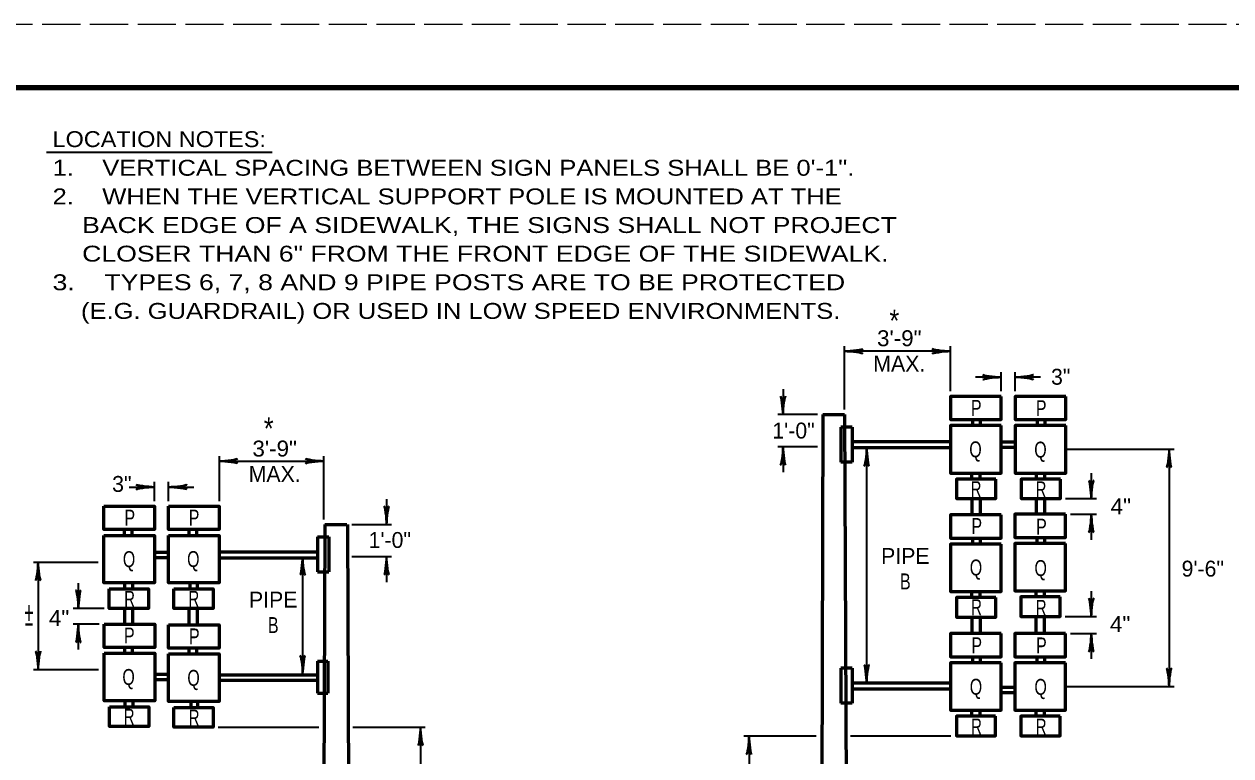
# Model space of a CAD drawing. Extents: x -209 to 471, y -242 to 199.
# Drawn here: x -54 to 135.5, y 83.5 to 198.5 of the extents above; entities that cross this region are included whole.
import ezdxf
from ezdxf.enums import TextEntityAlignment as Align

# ---------------------------------------------------------------- set-up
doc = ezdxf.new("R2010")
doc.units = 0
doc.linetypes.add('LONG_DASHED', pattern=[7.5, 6, -1.5])
doc.layers.add('1', color=7, linetype='Continuous', lineweight=53)
doc.layers.add('61', color=7, linetype='Continuous', lineweight=35)

msp = doc.modelspace()

# ---------------------------------------------------------------- linework, layer by layer
at = {"layer": '1', "lineweight": 35}
for p, q in [((-50.474, 178.398), (-15.047, 178.398)), ((74.868, 137.935), (74.868, 147.893)), ((91.488, 140.805), (91.488, 147.893)), ((91.488, 147.094), (74.868, 147.094)), ((99.434, 143.015), (95.441, 143.015)), ((99.434, 140.805), (99.434, 143.813)), ((101.648, 140.805), (101.648, 143.813)), ((105.641, 143.015), (101.648, 143.015)), ((65.201, 141.129), (65.201, 137.136)), ((70.633, 137.136), (64.402, 137.136)), ((70.633, 132.078), (64.402, 132.078)), ((65.201, 132.078), (65.201, 128.085)), ((78.33, 131.903), (78.33, 94.915)), ((109.594, 131.686), (126.631, 131.686)), ((125.832, 131.686), (125.832, 94.4)), ((-23.352, 129.823), (-6.91, 129.823)), ((-23.317, 123.534), (-23.317, 130.621)), ((-6.91, 120.663), (-6.91, 130.621)), ((113.605, 127.917), (113.605, 123.924)), ((-37.505, 125.743), (-33.512, 125.743)), ((-33.512, 123.534), (-33.512, 126.542)), ((-31.298, 123.534), (-31.298, 126.542)), ((-31.298, 125.743), (-27.305, 125.743)), ((2.935, 123.858), (2.935, 119.865)), ((109.552, 123.924), (114.403, 123.924)), ((110.339, 121.468), (114.403, 121.468)), ((113.605, 121.468), (113.605, 117.475)), ((-2.498, 119.865), (3.734, 119.865)), ((-52.505, 113.917), (-42.341, 113.917)), ((-51.779, 113.917), (-51.779, 97.063)), ((-10.241, 114.798), (-10.241, 96.392)), ((-2.498, 114.807), (3.734, 114.807)), ((2.935, 114.807), (2.935, 110.814)), ((-45.469, 110.645), (-45.469, 106.652)), ((113.605, 109.378), (113.605, 105.385)), ((-41.416, 106.652), (-46.267, 106.652)), ((109.499, 105.385), (114.403, 105.385)), ((-42.203, 104.197), (-46.267, 104.197)), ((-45.469, 104.197), (-45.469, 100.203)), ((110.339, 102.721), (114.403, 102.721)), ((113.605, 102.721), (113.605, 98.728)), ((-52.505, 97.063), (-42.293, 97.063)), ((109.541, 94.4), (126.631, 94.4)), ((-23.49, 88.009), (-7.724, 88.009)), ((-2.34, 88.009), (9.02, 88.009)), ((8.275, 88.009), (8.275, 58.346)), ((70.423, 86.607), (59.063, 86.607)), ((59.861, 86.607), (59.861, 56.943)), ((91.572, 86.607), (75.806, 86.607))]:
    msp.add_line(p, q, dxfattribs=at)
at = {"layer": '1'}
for p, q in [((71.432, 137.136), (71.21, 56.943)), ((71.432, 137.136), (74.868, 137.136)), ((74.868, 137.136), (75.201, 56.943)), ((76.031, 135.173), (74.285, 135.173)), ((74.285, 135.173), (74.285, 129.671)), ((76.031, 135.173), (76.031, 129.671)), ((95.004, 135.426), (95.004, 136.36)), ((96.189, 135.426), (96.189, 136.36)), ((105.164, 135.426), (105.164, 136.36)), ((106.349, 135.426), (106.349, 136.36)), ((91.455, 132.832), (76.031, 132.832)), ((101.723, 132.797), (99.509, 132.797)), ((91.455, 131.903), (76.031, 131.903)), ((101.723, 131.941), (99.509, 131.941)), ((76.031, 129.671), (74.285, 129.671)), ((94.871, 127.009), (94.871, 127.945)), ((96.162, 127.009), (96.162, 127.945)), ((105.031, 127.009), (105.031, 127.945)), ((106.322, 127.009), (106.322, 127.945)), ((94.897, 121.364), (94.897, 123.819)), ((96.189, 121.364), (96.189, 123.819)), ((105.031, 121.468), (105.031, 123.924)), ((106.322, 121.468), (106.322, 123.924)), ((-6.783, 119.865), (-6.954, 58.346)), ((-6.732, 119.865), (-3.296, 119.865)), ((-3.218, 119.865), (-2.963, 58.346)), ((-38.213, 118.154), (-38.213, 119.088)), ((-37.028, 118.154), (-37.028, 119.088)), ((-28.053, 118.154), (-28.053, 119.088)), ((-26.868, 118.154), (-26.868, 119.088)), ((-7.895, 117.901), (-6.149, 117.901)), ((-7.895, 117.901), (-7.895, 112.4)), ((-6.149, 117.901), (-6.149, 112.4)), ((95.004, 116.783), (95.004, 117.717)), ((96.189, 116.783), (96.189, 117.717)), ((105.111, 116.887), (105.111, 117.821)), ((106.295, 116.887), (106.295, 117.821)), ((-33.587, 115.526), (-31.374, 115.526)), ((-33.587, 114.669), (-31.374, 114.669)), ((-23.319, 115.561), (-7.895, 115.561)), ((-23.319, 114.632), (-7.895, 114.632)), ((-7.895, 112.4), (-6.149, 112.4)), ((-38.186, 109.738), (-38.186, 110.674)), ((-36.895, 109.738), (-36.895, 110.674)), ((-27.902, 109.761), (-27.902, 110.612)), ((-26.729, 109.761), (-26.729, 110.612)), ((94.871, 108.367), (94.871, 109.303)), ((96.162, 108.367), (96.162, 109.303)), ((104.978, 108.471), (104.978, 109.407)), ((106.269, 108.471), (106.269, 109.407)), ((-38.186, 104.197), (-38.186, 106.652)), ((-36.895, 104.197), (-36.895, 106.652)), ((-28.053, 104.092), (-28.053, 106.548)), ((-26.762, 104.092), (-26.762, 106.548)), ((94.895, 102.721), (94.895, 105.176)), ((96.186, 102.721), (96.186, 105.176)), ((104.978, 102.721), (104.978, 105.385)), ((106.269, 102.721), (106.269, 105.385)), ((-38.16, 99.616), (-38.16, 100.55)), ((-36.975, 99.616), (-36.975, 100.55)), ((-28.053, 99.511), (-28.053, 100.445)), ((-26.868, 99.511), (-26.868, 100.445)), ((95.002, 98.14), (95.002, 99.074)), ((96.186, 98.14), (96.186, 99.074)), ((105.111, 98.14), (105.111, 99.074)), ((106.295, 98.14), (106.295, 99.074)), ((-7.895, 98.353), (-6.308, 98.353)), ((-7.895, 98.353), (-7.895, 93.352)), ((-6.308, 98.353), (-6.308, 93.352)), ((76.031, 97.255), (74.285, 97.255)), ((74.285, 97.255), (74.285, 91.753)), ((76.031, 97.255), (76.031, 91.753)), ((-33.397, 96.348), (-31.183, 96.348)), ((-33.397, 95.492), (-31.183, 95.492)), ((-23.352, 96.226), (-7.895, 96.226)), ((-23.352, 95.381), (-7.895, 95.381)), ((91.455, 94.915), (76.031, 94.915)), ((-7.895, 93.352), (-6.308, 93.352)), ((91.455, 93.985), (76.031, 93.985)), ((101.59, 94.26), (99.376, 94.26)), ((101.59, 93.404), (99.376, 93.404)), ((-38.133, 91.199), (-38.133, 92.135)), ((-36.842, 91.199), (-36.842, 92.135)), ((-27.807, 91.946), (-27.807, 91.095)), ((-26.73, 91.946), (-26.73, 91.095)), ((76.031, 91.753), (74.285, 91.753)), ((94.869, 89.724), (94.869, 90.66)), ((96.16, 89.724), (96.16, 90.66)), ((104.978, 89.724), (104.978, 90.66)), ((106.269, 89.724), (106.269, 90.66))]:
    msp.add_line(p, q, dxfattribs=at)
for points in [[(99.434, 140.006), (91.488, 140.006), (91.488, 136.36), (99.434, 136.36)], [(109.594, 140.006), (101.648, 140.006), (101.648, 136.36), (109.594, 136.36)], [(99.434, 135.426), (91.488, 135.426), (91.488, 127.945), (99.434, 127.945)], [(109.594, 135.426), (101.648, 135.426), (101.648, 127.945), (109.594, 127.945)], [(98.593, 127.009), (92.424, 127.009), (92.424, 123.924), (98.593, 123.924)], [(108.753, 127.009), (102.584, 127.009), (102.584, 123.924), (108.753, 123.924)], [(-41.458, 122.735), (-33.512, 122.735), (-33.512, 119.088), (-41.458, 119.088)], [(-31.298, 122.735), (-23.352, 122.735), (-23.352, 119.088), (-31.298, 119.088)], [(99.434, 121.364), (91.488, 121.364), (91.488, 117.717), (99.434, 117.717)], [(109.541, 121.468), (101.595, 121.468), (101.595, 117.821), (109.541, 117.821)], [(-41.458, 118.154), (-33.512, 118.154), (-33.512, 110.674), (-41.458, 110.674)], [(-31.298, 118.154), (-23.352, 118.154), (-23.352, 110.674), (-31.298, 110.674)], [(99.434, 116.783), (91.488, 116.783), (91.488, 109.303), (99.434, 109.303)], [(109.541, 116.887), (101.595, 116.887), (101.595, 109.407), (109.541, 109.407)], [(-40.617, 109.738), (-34.448, 109.738), (-34.448, 106.652), (-40.617, 106.652)], [(-30.457, 109.738), (-24.288, 109.738), (-24.288, 106.652), (-30.457, 106.652)], [(98.593, 108.367), (92.424, 108.367), (92.424, 105.281), (98.593, 105.281)], [(108.7, 108.471), (102.531, 108.471), (102.531, 105.385), (108.7, 105.385)], [(-41.405, 104.197), (-33.459, 104.197), (-33.459, 100.55), (-41.405, 100.55)], [(-31.298, 104.092), (-23.352, 104.092), (-23.352, 100.445), (-31.298, 100.445)], [(99.432, 102.721), (91.486, 102.721), (91.486, 99.074), (99.432, 99.074)], [(109.541, 102.721), (101.595, 102.721), (101.595, 99.074), (109.541, 99.074)], [(-41.405, 99.616), (-33.459, 99.616), (-33.459, 92.135), (-41.405, 92.135)], [(-31.298, 99.511), (-23.352, 99.511), (-23.352, 92.031), (-31.298, 92.031)], [(99.432, 98.14), (91.486, 98.14), (91.486, 90.66), (99.432, 90.66)], [(109.541, 98.14), (101.595, 98.14), (101.595, 90.66), (109.541, 90.66)], [(-40.564, 91.199), (-34.395, 91.199), (-34.395, 88.114), (-40.564, 88.114)], [(-30.457, 91.095), (-24.288, 91.095), (-24.288, 88.009), (-30.457, 88.009)], [(98.591, 89.724), (92.422, 89.724), (92.422, 86.638), (98.591, 86.638)], [(108.7, 89.724), (102.531, 89.724), (102.531, 86.638), (108.7, 86.638)]]:
    msp.add_lwpolyline(points, close=True, dxfattribs=at)
at = {"layer": '1', "lineweight": 40}
for centre, major_axis, ratio, start_param, end_param in [((75.989, 147.306), (-1.756, -0.176), 0.07063, 0.8650754, 3.1424706), ((75.959, 146.818), (-1.786, 0.156), 0.122415, 3.1415927, 5.386832), ((90.397, 147.37), (1.786, -0.156), 0.122415, 3.1415927, 5.386832), ((90.397, 147.37), (1.786, -0.156), 0.122415, 3.1415927, 5.386832), ((90.367, 146.882), (1.756, 0.176), 0.07063, 0.8650754, 3.1424706), ((90.367, 146.882), (1.756, 0.176), 0.07063, 0.8650754, 3.1424706), ((98.343, 143.291), (1.786, -0.156), 0.122415, 3.1415927, 5.386832), ((98.313, 142.803), (1.756, 0.176), 0.07063, 0.8650754, 3.1424706), ((102.768, 143.226), (-1.756, -0.176), 0.07063, 0.8650754, 3.1424706), ((102.739, 142.738), (-1.786, 0.156), 0.122415, 3.1415927, 5.386832), ((64.989, 138.257), (0.176, -1.756), 0.07063, 0.8650754, 3.1424706), ((65.477, 138.227), (-0.156, -1.786), 0.122415, 3.1415927, 5.386832), ((64.924, 130.987), (0.156, 1.786), 0.122415, 3.1415927, 5.386832), ((64.924, 130.987), (0.156, 1.786), 0.122415, 3.1415927, 5.386832), ((65.412, 130.958), (-0.176, 1.756), 0.07063, 0.8650754, 3.1424706), ((65.412, 130.958), (-0.176, 1.756), 0.07063, 0.8650754, 3.1424706), ((78.054, 130.812), (0.156, 1.786), 0.122415, 3.1415927, 5.386832), ((78.542, 130.782), (-0.176, 1.756), 0.07063, 0.8650754, 3.1424706), ((125.556, 130.594), (0.156, 1.786), 0.122415, 3.1415927, 5.386832), ((125.556, 130.594), (0.156, 1.786), 0.122415, 3.1415927, 5.386832), ((126.044, 130.565), (-0.176, 1.756), 0.07063, 0.8650754, 3.1424706), ((126.044, 130.565), (-0.176, 1.756), 0.07063, 0.8650754, 3.1424706), ((-22.232, 129.611), (-1.756, 0.176), 0.07063, 3.1407148, 5.41811), ((-22.232, 129.611), (-1.756, 0.176), 0.07063, 3.1407148, 5.41811), ((-22.261, 130.099), (-1.786, -0.156), 0.122415, 0.8963533, 3.1415927), ((-22.261, 130.099), (-1.786, -0.156), 0.122415, 0.8963533, 3.1415927), ((-8.001, 129.546), (1.786, 0.156), 0.122415, 0.8963533, 3.1415927), ((-8.03, 130.034), (1.756, -0.176), 0.07063, 3.1407148, 5.41811), ((-34.603, 125.467), (1.786, 0.156), 0.122415, 0.8963533, 3.1415927), ((-34.633, 125.955), (1.756, -0.176), 0.07063, 3.1407148, 5.41811), ((-30.178, 125.532), (-1.756, 0.176), 0.07063, 3.1407148, 5.41811), ((-30.207, 126.019), (-1.786, -0.156), 0.122415, 0.8963533, 3.1415927), ((113.393, 125.044), (0.176, -1.756), 0.07063, 0.8650754, 3.1424706), ((113.393, 125.044), (0.176, -1.756), 0.07063, 0.8650754, 3.1424706), ((113.881, 125.015), (-0.156, -1.786), 0.122415, 3.1415927, 5.386832), ((113.881, 125.015), (-0.156, -1.786), 0.122415, 3.1415927, 5.386832), ((2.659, 120.956), (0.156, -1.786), 0.122415, 0.8963533, 3.1415927), ((3.147, 120.985), (-0.176, -1.756), 0.07063, 3.1407148, 5.41811), ((113.328, 120.377), (0.156, 1.786), 0.122415, 3.1415927, 5.386832), ((113.328, 120.377), (0.156, 1.786), 0.122415, 3.1415927, 5.386832), ((113.816, 120.347), (-0.176, 1.756), 0.07063, 0.8650754, 3.1424706), ((113.816, 120.347), (-0.176, 1.756), 0.07063, 0.8650754, 3.1424706), ((-51.991, 112.796), (0.176, 1.756), 0.07063, 3.1407148, 5.41811), ((-51.991, 112.796), (0.176, 1.756), 0.07063, 3.1407148, 5.41811), ((-51.503, 112.825), (-0.156, 1.786), 0.122415, 0.8963533, 3.1415927), ((-51.503, 112.825), (-0.156, 1.786), 0.122415, 0.8963533, 3.1415927), ((-10.453, 113.678), (0.176, 1.756), 0.07063, 3.1407148, 5.41811), ((-9.965, 113.707), (-0.156, 1.786), 0.122415, 0.8963533, 3.1415927), ((2.724, 113.686), (0.176, 1.756), 0.07063, 3.1407148, 5.41811), ((3.211, 113.716), (-0.156, 1.786), 0.122415, 0.8963533, 3.1415927), ((-45.745, 107.743), (0.156, -1.786), 0.122415, 0.8963533, 3.1415927), ((-45.257, 107.773), (-0.176, -1.756), 0.07063, 3.1407148, 5.41811), ((113.393, 106.506), (0.176, -1.756), 0.07063, 0.8650754, 3.1424706), ((113.393, 106.506), (0.176, -1.756), 0.07063, 0.8650754, 3.1424706), ((113.881, 106.476), (-0.156, -1.786), 0.122415, 3.1415927, 5.386832), ((113.881, 106.476), (-0.156, -1.786), 0.122415, 3.1415927, 5.386832), ((-45.68, 103.076), (0.176, 1.756), 0.07063, 3.1407148, 5.41811), ((-45.193, 103.105), (-0.156, 1.786), 0.122415, 0.8963533, 3.1415927), ((113.328, 101.63), (0.156, 1.786), 0.122415, 3.1415927, 5.386832), ((113.328, 101.63), (0.156, 1.786), 0.122415, 3.1415927, 5.386832), ((113.816, 101.6), (-0.176, 1.756), 0.07063, 0.8650754, 3.1424706), ((113.816, 101.6), (-0.176, 1.756), 0.07063, 0.8650754, 3.1424706), ((-52.056, 98.154), (0.156, -1.786), 0.122415, 0.8963533, 3.1415927), ((-52.056, 98.154), (0.156, -1.786), 0.122415, 0.8963533, 3.1415927), ((-51.568, 98.184), (-0.176, -1.756), 0.07063, 3.1407148, 5.41811), ((-51.568, 98.184), (-0.176, -1.756), 0.07063, 3.1407148, 5.41811), ((-10.518, 97.483), (0.156, -1.786), 0.122415, 0.8963533, 3.1415927), ((-10.518, 97.483), (0.156, -1.786), 0.122415, 0.8963533, 3.1415927), ((-10.03, 97.513), (-0.176, -1.756), 0.07063, 3.1407148, 5.41811), ((-10.03, 97.513), (-0.176, -1.756), 0.07063, 3.1407148, 5.41811), ((78.119, 96.035), (0.176, -1.756), 0.07063, 0.8650754, 3.1424706), ((78.119, 96.035), (0.176, -1.756), 0.07063, 0.8650754, 3.1424706), ((78.607, 96.006), (-0.156, -1.786), 0.122415, 3.1415927, 5.386832), ((78.607, 96.006), (-0.156, -1.786), 0.122415, 3.1415927, 5.386832), ((125.621, 95.52), (0.176, -1.756), 0.07063, 0.8650754, 3.1424706), ((125.621, 95.52), (0.176, -1.756), 0.07063, 0.8650754, 3.1424706), ((126.108, 95.491), (-0.156, -1.786), 0.122415, 3.1415927, 5.386832), ((126.108, 95.491), (-0.156, -1.786), 0.122415, 3.1415927, 5.386832), ((8.063, 86.889), (0.176, 1.756), 0.07063, 3.1407148, 5.41811), ((8.063, 86.889), (0.176, 1.756), 0.07063, 3.1407148, 5.41811), ((8.551, 86.918), (-0.156, 1.786), 0.122415, 0.8963533, 3.1415927), ((8.551, 86.918), (-0.156, 1.786), 0.122415, 0.8963533, 3.1415927), ((59.585, 85.516), (0.156, 1.786), 0.122415, 3.1415927, 5.386832), ((60.073, 85.486), (-0.176, 1.756), 0.07063, 0.8650754, 3.1424706)]:
    msp.add_ellipse(centre, major_axis=major_axis, ratio=ratio, start_param=start_param, end_param=end_param, dxfattribs=at)
at = {"layer": '61', "linetype": 'LONG_DASHED', "lineweight": 13}
msp.add_line((-208.646, 198.515), (471.374, 198.515), dxfattribs=at)
at = {"layer": '61', "lineweight": 158}
msp.add_lwpolyline([(460.394, 188.515), (-178.646, 188.515), (-178.646, -231.505)], dxfattribs=at)

# ---------------------------------------------------------------- texts
at = {"layer": '1'}
for s, width, p in [('LOCATION NOTES:', 1.1, (-49.514, 179.183)), ('1.    VERTICAL SPACING BETWEEN SIGN PANELS SHALL BE 0\'-1".', 1.2, (-49.514, 174.683)), ('2.    WHEN THE VERTICAL SUPPORT POLE IS MOUNTED AT THE', 1.2, (-49.514, 170.183)), ('    BACK EDGE OF A SIDEWALK, THE SIGNS SHALL NOT PROJECT', 1.25, (-49.514, 165.683)), ('    CLOSER THAN 6" FROM THE FRONT EDGE OF THE SIDEWALK.', 1.25, (-49.514, 161.183)), ('3.    TYPES 6, 7, 8 AND 9 PIPE POSTS ARE TO BE PROTECTED', 1.25, (-49.514, 156.683)), ('    (E.G. GUARDRAIL) OR USED IN LOW SPEED ENVIRONMENTS.', 1.2, (-49.514, 152.183))]:
    msp.add_text(s, height=2.5, dxfattribs=dict(at, width=width)).set_placement(p)
for s, height, width, p in [('*', 3.5, 0.85, (82.682, 150.145)), ('3\'-9"', 2.5, 1.05, (83.461, 147.89)), ('P', 2.5, 0.75, (95.542, 136.936)), ('P', 2.5, 0.75, (105.743, 136.896)), ('*', 3.5, 0.85, (-15.571, 133.205)), ('3\'-9"', 2.5, 1.05, (-14.631, 130.547)), ('Q', 2.5, 0.75, (95.425, 130.422)), ('Q', 2.5, 0.75, (105.626, 130.381)), ('R', 2.5, 0.7, (95.513, 124.169)), ('R', 2.5, 0.7, (105.714, 124.129)), ('4"', 2.5, 1.05, (118.247, 121.473)), ('P', 2.5, 0.75, (-37.388, 119.678)), ('P', 2.5, 0.75, (-27.296, 119.689)), ('P', 2.5, 0.75, (95.62, 118.365)), ('P', 2.5, 0.75, (105.779, 118.272)), ('Q', 2.5, 0.75, (-37.504, 113.164)), ('Q', 2.5, 0.75, (-27.412, 113.175)), ('Q', 2.5, 0.75, (95.503, 111.851)), ('Q', 2.5, 0.75, (105.662, 111.758)), ('B', 2.5, 0.75, (84.41, 109.663)), ('R', 2.5, 0.7, (-37.417, 106.911)), ('R', 2.5, 0.7, (-27.325, 106.922)), ('R', 2.5, 0.7, (95.591, 105.598)), ('+', 3.5, 0.55, (-53.214, 104.261)), ('4"', 2.5, 1.05, (-48.489, 103.917)), ('R', 2.5, 0.7, (105.75, 105.505)), ('B', 2.5, 0.75, (-14.861, 102.801)), ('4"', 2.5, 1.05, (118.143, 102.954)), ('P', 2.5, 0.75, (-37.461, 101.156)), ('P', 2.5, 0.75, (-27.256, 101.015)), ('P', 2.5, 0.75, (95.616, 99.617)), ('P', 2.5, 0.75, (105.773, 99.599)), ('Q', 2.5, 0.75, (-37.577, 94.642)), ('Q', 2.5, 0.75, (-27.373, 94.5)), ('Q', 2.5, 0.75, (95.5, 93.103)), ('Q', 2.5, 0.75, (105.656, 93.085)), ('R', 2.5, 0.7, (-37.49, 88.389)), ('R', 2.5, 0.7, (-27.285, 88.248)), ('R', 2.5, 0.7, (95.587, 86.85)), ('R', 2.5, 0.7, (105.743, 86.832))]:
    msp.add_text(s, height=height, dxfattribs=dict(at, width=width)).set_placement(p, align=Align.CENTER)
for s, height, p in [('MAX.', 2.5, (83.461, 143.89)), ('3"', 2.5, (108.808, 141.831)), ('1\'-0"', 2.5, (66.847, 133.373)), ('MAX.', 2.5, (-14.631, 126.547)), ('3"', 2.5, (-38.636, 124.984)), ('1\'-0"', 2.5, (3.441, 116.175)), ('PIPE', 2.5, (84.41, 113.663)), ('9\'-6"', 2.5, (131.122, 111.674)), ('PIPE', 2.5, (-14.861, 106.801)), ('-', 3.5, (-53.214, 102.791))]:
    msp.add_text(s, height=height, dxfattribs=at).set_placement(p, align=Align.CENTER)

doc.saveas('drawing.dxf')
